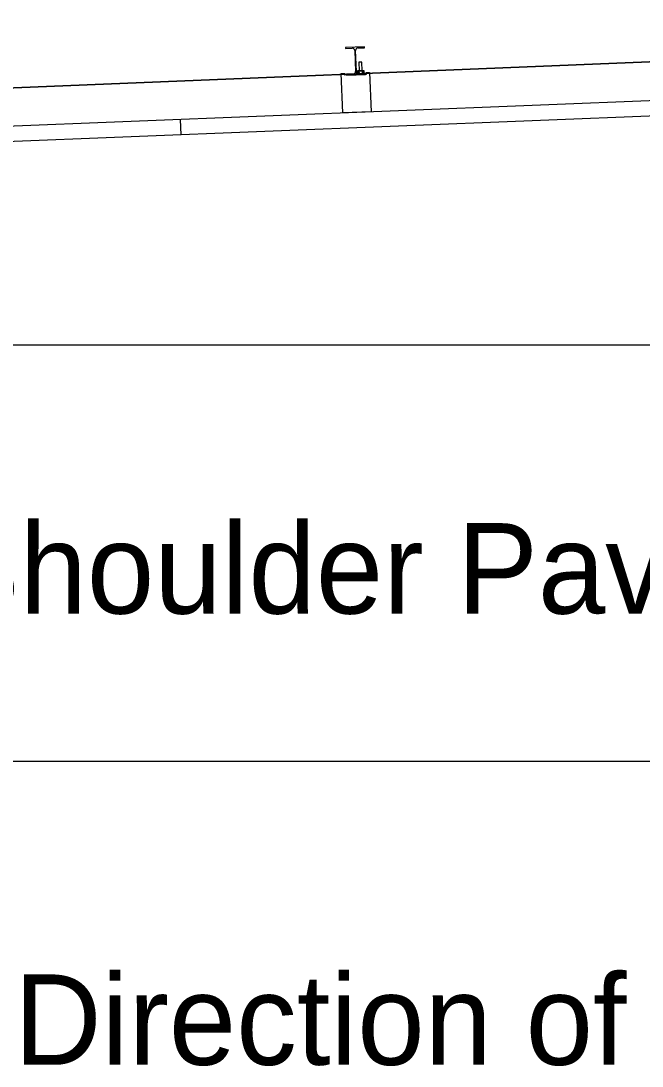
# Model space of a CAD drawing. Extents: x 9538 to 81668, y 7600 to 11751.
# Drawn here: x 25609.3 to 25719.1, y 9572.7 to 9757.6 of the extents above; entities that cross this region are included whole.
import ezdxf

# ---------------------------------------------------------------- set-up
doc = ezdxf.new("R2010")
doc.units = 0
for name, color, linetype in [('dsnStdCells', 7, 'Continuous'), ('dsnStdDimension', 7, 'Continuous'), ('dsnStdNote', 7, 'Continuous'), ('dsnStdTable', 7, 'Continuous')]:
    doc.layers.add(name, color=color, linetype=linetype)

msp = doc.modelspace()

# ---------------------------------------------------------------- linework, layer by layer
at = {"layer": 'dsnStdCells'}
for p, q in [((25670.01, 9753.03), (25666.68, 9752.9)), ((25670.01, 9753.03), (25666.68, 9752.9)), ((25666.68, 9752.9), (25666.69, 9752.74)), ((25666.68, 9752.9), (25666.69, 9752.74)), ((25666.69, 9752.74), (25667.86, 9752.79)), ((25666.69, 9752.74), (25667.86, 9752.79)), ((25668.29, 9752.39), (25668.44, 9748.64)), ((25668.29, 9752.39), (25668.44, 9748.64)), ((25668.6, 9748.65), (25668.45, 9752.39)), ((25668.6, 9748.65), (25668.45, 9752.39)), ((25668.85, 9752.83), (25670.02, 9752.87)), ((25668.85, 9752.83), (25670.02, 9752.87)), ((25670.02, 9752.87), (25670.01, 9753.03)), ((25670.02, 9752.87), (25670.01, 9753.03)), ((25669.55, 9750.3), (25669.03, 9750.28)), ((25669.55, 9750.3), (25669.03, 9750.28)), ((25669.03, 9750.28), (25669.09, 9748.77)), ((25669.03, 9750.28), (25669.09, 9748.77)), ((25669.61, 9748.79), (25669.55, 9750.3)), ((25669.61, 9748.79), (25669.55, 9750.3)), ((25665.93, 9748.28), (25666.55, 9748.3)), ((25666.21, 9741.32), (25665.93, 9748.28)), ((25666.57, 9747.99), (25666.55, 9748.3)), ((25670.31, 9748.14), (25666.57, 9747.99)), ((25668.04, 9748.21), (25666.87, 9748.16)), ((25668.04, 9748.21), (25666.87, 9748.16)), ((25666.87, 9748.16), (25666.88, 9748)), ((25666.87, 9748.16), (25666.88, 9748)), ((25666.88, 9748), (25670.21, 9748.14)), ((25666.88, 9748), (25670.21, 9748.14)), ((25668.83, 9748.76), (25668.75, 9748.7)), ((25668.83, 9748.76), (25668.75, 9748.7)), ((25668.75, 9748.7), (25668.77, 9748.33)), ((25668.77, 9748.33), (25668.75, 9748.7)), ((25669.8, 9748.8), (25668.83, 9748.76)), ((25668.83, 9748.76), (25669.8, 9748.8)), ((25670.2, 9748.29), (25669.03, 9748.25)), ((25670.2, 9748.29), (25669.03, 9748.25)), ((25669.05, 9748.72), (25669.07, 9748.3)), ((25669.07, 9748.3), (25669.05, 9748.72)), ((25669.07, 9748.3), (25669.05, 9748.72)), ((25669.09, 9748.77), (25669.61, 9748.79)), ((25669.67, 9748.32), (25669.65, 9748.74)), ((25669.65, 9748.74), (25669.67, 9748.32)), ((25669.67, 9748.32), (25669.65, 9748.74)), ((25669.87, 9748.8), (25669.8, 9748.8)), ((25669.8, 9748.8), (25669.87, 9748.8)), ((25669.95, 9748.75), (25669.87, 9748.8)), ((25669.95, 9748.75), (25669.87, 9748.8)), ((25669.89, 9748.28), (25669.97, 9748.34)), ((25669.89, 9748.28), (25669.97, 9748.34)), ((25669.97, 9748.34), (25669.95, 9748.75)), ((25669.97, 9748.34), (25669.95, 9748.75)), ((25670.21, 9748.14), (25670.2, 9748.29)), ((25670.21, 9748.14), (25670.2, 9748.29)), ((25670.3, 9748.45), (25670.93, 9748.48)), ((25670.3, 9748.45), (25670.31, 9748.14)), ((25670.93, 9748.48), (25671.2, 9741.52)), ((25671.2, 9741.52), (25666.21, 9741.32))]:
    msp.add_line(p, q, dxfattribs=at)
for points in [[(25668.77, 9748.33), (25668.77, 9748.33)], [(25669.03, 9748.25), (25669.89, 9748.28), (25669.89, 9748.28)]]:
    msp.add_lwpolyline(points, dxfattribs=at)
for centre, start, end in [((25667.88, 9752.37), 2.2841, 92.2932), ((25667.88, 9752.37), 2.2841, 92.2932), ((25668.87, 9752.41), 92.2981, 182.2871), ((25668.87, 9752.41), 92.2981, 182.2871), ((25668.03, 9748.62), 272.2981, 2.2871), ((25668.03, 9748.62), 272.2981, 2.2871), ((25669.02, 9748.66), 182.2841, 272.2932), ((25669.02, 9748.66), 182.2841, 272.2932), ((25669.02, 9748.66), 233.1773, 272.2932)]:
    msp.add_arc(centre, 0.417, start, end, dxfattribs=at)
for points in [[(25669.05, 9748.72), (25669.02, 9748.73), (25668.97, 9748.76), (25668.89, 9748.77), (25668.81, 9748.74), (25668.77, 9748.72), (25668.75, 9748.7)], [(25668.75, 9748.7), (25668.77, 9748.72), (25668.81, 9748.74), (25668.89, 9748.77), (25668.97, 9748.76), (25669.02, 9748.73), (25669.05, 9748.72)], [(25669.05, 9748.72), (25669.02, 9748.73), (25668.97, 9748.76), (25668.89, 9748.77), (25668.81, 9748.74), (25668.77, 9748.72), (25668.75, 9748.7)], [(25668.97, 9748.25), (25668.98, 9748.26), (25669.02, 9748.26), (25669.05, 9748.29), (25669.07, 9748.3)], [(25669.65, 9748.74), (25669.6, 9748.75), (25669.49, 9748.78), (25669.33, 9748.78), (25669.19, 9748.76), (25669.1, 9748.73), (25669.05, 9748.72)], [(25669.05, 9748.72), (25669.1, 9748.73), (25669.19, 9748.76), (25669.33, 9748.78), (25669.49, 9748.78), (25669.6, 9748.75), (25669.65, 9748.74)], [(25669.65, 9748.74), (25669.6, 9748.75), (25669.49, 9748.78), (25669.33, 9748.78), (25669.19, 9748.76), (25669.1, 9748.73), (25669.05, 9748.72)], [(25669.07, 9748.3), (25669.12, 9748.29), (25669.23, 9748.26), (25669.39, 9748.26), (25669.53, 9748.28), (25669.62, 9748.31), (25669.67, 9748.32)], [(25669.67, 9748.32), (25669.62, 9748.31), (25669.53, 9748.28), (25669.39, 9748.26), (25669.23, 9748.26), (25669.12, 9748.29), (25669.07, 9748.3)], [(25669.07, 9748.3), (25669.12, 9748.29), (25669.23, 9748.26), (25669.39, 9748.26), (25669.53, 9748.28), (25669.62, 9748.31), (25669.67, 9748.32)], [(25669.95, 9748.75), (25669.93, 9748.76), (25669.9, 9748.78), (25669.84, 9748.8), (25669.76, 9748.8), (25669.7, 9748.77), (25669.66, 9748.75), (25669.65, 9748.74)], [(25669.65, 9748.74), (25669.66, 9748.75), (25669.7, 9748.77), (25669.76, 9748.8), (25669.84, 9748.8), (25669.9, 9748.78), (25669.93, 9748.76), (25669.95, 9748.75)], [(25669.95, 9748.75), (25669.93, 9748.76), (25669.9, 9748.78), (25669.84, 9748.8), (25669.76, 9748.8), (25669.7, 9748.77), (25669.66, 9748.75), (25669.65, 9748.74)], [(25669.67, 9748.32), (25669.68, 9748.32), (25669.72, 9748.3), (25669.78, 9748.28), (25669.86, 9748.28), (25669.92, 9748.3), (25669.95, 9748.33), (25669.97, 9748.34)], [(25669.97, 9748.34), (25669.95, 9748.33), (25669.92, 9748.3), (25669.86, 9748.28), (25669.78, 9748.28), (25669.72, 9748.3), (25669.68, 9748.32), (25669.67, 9748.32)], [(25669.67, 9748.32), (25669.68, 9748.32), (25669.72, 9748.3), (25669.78, 9748.28), (25669.86, 9748.28), (25669.92, 9748.3), (25669.95, 9748.33), (25669.97, 9748.34)]]:
    msp.add_open_spline(points, degree=3, dxfattribs=at)
at = {"layer": 'dsnStdDimension'}
for p, q in [((25896.12, 9757.6), (25420.83, 9738.08)), ((25169.17, 9700.29), (26200.86, 9700.29))]:
    msp.add_line(p, q, dxfattribs=at)
at = {"layer": 'dsnStdTable'}
for p, q in [((25420.73, 9738.08), (25896.12, 9757.6)), ((25670.01, 9753.03), (25666.68, 9752.9)), ((25666.68, 9752.9), (25666.69, 9752.74)), ((25666.69, 9752.74), (25667.86, 9752.79)), ((25668.29, 9752.39), (25668.44, 9748.64)), ((25668.6, 9748.65), (25668.45, 9752.39)), ((25668.85, 9752.83), (25670.02, 9752.87)), ((25670.02, 9752.87), (25670.01, 9753.03)), ((25669.55, 9750.3), (25669.03, 9750.28)), ((25669.03, 9750.28), (25669.09, 9748.77)), ((25669.61, 9748.79), (25669.55, 9750.3)), ((25665.93, 9748.28), (25666.55, 9748.3)), ((25666.21, 9741.32), (25665.93, 9748.28)), ((25666.57, 9747.99), (25666.55, 9748.3)), ((25670.31, 9748.14), (25666.57, 9747.99)), ((25668.04, 9748.21), (25666.87, 9748.16)), ((25666.87, 9748.16), (25666.88, 9748)), ((25666.88, 9748), (25670.21, 9748.14)), ((25668.83, 9748.76), (25668.75, 9748.7)), ((25668.77, 9748.33), (25668.75, 9748.7)), ((25668.83, 9748.76), (25669.8, 9748.8)), ((25670.2, 9748.29), (25669.03, 9748.25)), ((25669.07, 9748.3), (25669.05, 9748.72)), ((25669.67, 9748.32), (25669.65, 9748.74)), ((25669.8, 9748.8), (25669.87, 9748.8)), ((25669.95, 9748.75), (25669.87, 9748.8)), ((25669.89, 9748.28), (25669.97, 9748.34)), ((25669.97, 9748.34), (25669.95, 9748.75)), ((25670.21, 9748.14), (25670.2, 9748.29)), ((25670.3, 9748.45), (25670.93, 9748.48)), ((25670.3, 9748.45), (25670.31, 9748.14)), ((25670.93, 9748.48), (25671.2, 9741.52)), ((25799.33, 9746.65), (25387.76, 9730.18)), ((25799.44, 9743.94), (25387.76, 9727.47)), ((25671.2, 9741.52), (25666.21, 9741.32)), ((25637.48, 9740.17), (25637.59, 9737.47)), ((24764.02, 9700.29), (26377.72, 9700.29)), ((24764.23, 9626.66), (26378.02, 9626.66))]:
    msp.add_line(p, q, dxfattribs=at)
for centre, start, end in [((25667.88, 9752.37), 2.2841, 92.2932), ((25668.87, 9752.41), 92.2981, 182.2871), ((25668.03, 9748.62), 272.2981, 2.2871), ((25669.02, 9748.66), 182.2841, 272.2932)]:
    msp.add_arc(centre, 0.417, start, end, dxfattribs=at)
for points in [[(25669.05, 9748.72), (25669.02, 9748.73), (25668.97, 9748.76), (25668.89, 9748.77), (25668.81, 9748.74), (25668.77, 9748.72), (25668.75, 9748.7)], [(25668.97, 9748.25), (25668.98, 9748.26), (25669.02, 9748.26), (25669.05, 9748.29), (25669.07, 9748.3)], [(25669.65, 9748.74), (25669.6, 9748.75), (25669.49, 9748.78), (25669.33, 9748.78), (25669.19, 9748.76), (25669.1, 9748.73), (25669.05, 9748.72)], [(25669.07, 9748.3), (25669.12, 9748.29), (25669.23, 9748.26), (25669.39, 9748.26), (25669.53, 9748.28), (25669.62, 9748.31), (25669.67, 9748.32)], [(25669.95, 9748.75), (25669.93, 9748.76), (25669.9, 9748.78), (25669.84, 9748.8), (25669.76, 9748.8), (25669.7, 9748.77), (25669.66, 9748.75), (25669.65, 9748.74)], [(25669.67, 9748.32), (25669.68, 9748.32), (25669.72, 9748.3), (25669.78, 9748.28), (25669.86, 9748.28), (25669.92, 9748.3), (25669.95, 9748.33), (25669.97, 9748.34)]]:
    msp.add_open_spline(points, degree=3, dxfattribs=at)

# ---------------------------------------------------------------- texts
at = {"layer": 'dsnStdNote'}
for s, p in [('Edge of Shoulder Pavement', (25515.11, 9652.77)), ('Direction of Traffic', (25608.13, 9572.96))]:
    msp.add_text(s, height=16, dxfattribs=at).set_placement(p)

doc.saveas('drawing.dxf')
